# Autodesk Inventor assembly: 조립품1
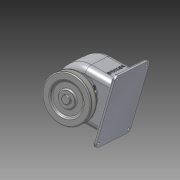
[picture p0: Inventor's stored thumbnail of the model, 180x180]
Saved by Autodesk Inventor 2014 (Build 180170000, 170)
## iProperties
Created: 2016-01
Part Number: 조립품1
Document SubType Name: Assembly
Designer: SEC
Author: SEC
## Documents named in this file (16)
- C:\Users\SEC\Desktop\조립품1.iam
- C:\Users\SEC\Desktop\부품1.ipt
- C:\Users\SEC\Desktop\460105V1007\V-벨트풀리.ipt
- C:\Users\SEC\Desktop\460105V1007\뒤커버.ipt
- C:\Users\SEC\Desktop\460105V1007\멈춤나사 - M4x10.ipt
- C:\Users\SEC\Desktop\460105V1007\베어링 6203.ipt
- C:\Users\SEC\Desktop\460105V1007\볼트 M3 x 8.ipt
- C:\Users\SEC\Desktop\460105V1007\볼트 M3 x 10.ipt
- C:\Users\SEC\Desktop\460105V1007\부시1.ipt
- C:\Users\SEC\Desktop\460105V1007\부시2.ipt
- C:\Users\SEC\Desktop\460105V1007\스퍼기어.ipt
- C:\Users\SEC\Desktop\460105V1007\앞커버.ipt
- C:\Users\SEC\Desktop\460105V1007\오일씰 28 40 8.ipt
- C:\Users\SEC\Desktop\460105V1007\축.ipt
- C:\Users\SEC\Desktop\460105V1007\키 - 5 x 5 x 18.ipt
- C:\Users\SEC\Desktop\460105V1007\키 - 6 x 6 x 22.ipt
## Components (9 placed, 3 different names)
1. V-벨트풀리:1 — 각도:6
2. ISO 4762 M3 x 8:1 — 각도:4
3. ISO 4762 M3 x 8:2
4. ISO 4762 M3 x 8:3
5. ISO 4762 M3 x 8:4
6. ISO 4762 M3 x 10:1 — 각도:5
7. ISO 4762 M3 x 10:2
8. ISO 4762 M3 x 10:3
9. ISO 4762 M3 x 10:4
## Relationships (3: Angle 3)
- 각도:4 [Angle]: ISO 4762 M3 x 8:1
- 각도:5 [Angle]: ISO 4762 M3 x 10:1
- 각도:6 [Angle]: V-벨트풀리:1
